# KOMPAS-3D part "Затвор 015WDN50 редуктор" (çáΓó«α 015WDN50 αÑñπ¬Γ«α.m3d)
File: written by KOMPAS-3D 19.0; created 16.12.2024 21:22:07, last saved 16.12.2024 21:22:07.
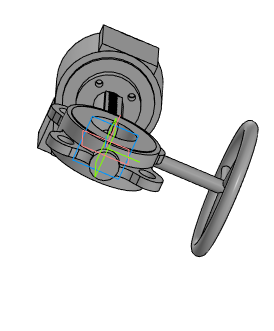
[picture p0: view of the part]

Document properties: Автор: Евгений; Полное имя файла: ..\Затвор 015WDN50 редуктор.a3d

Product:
- Part/product: Затвор 015WDN50 редуктор
    Масса: 9.61817

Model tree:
1. Операция без истории:1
